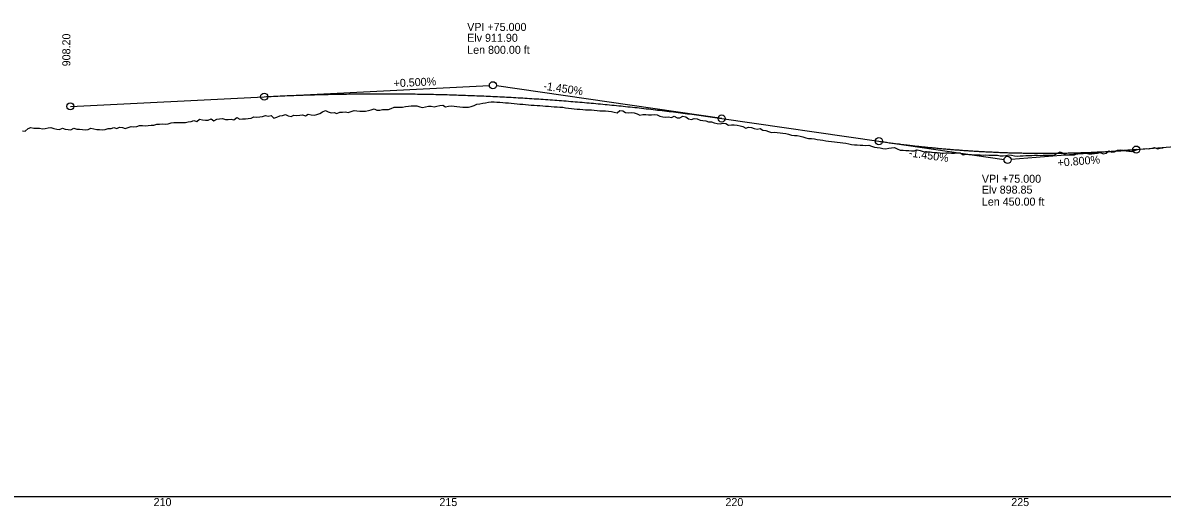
# Model space of a CAD drawing. Extents: x 5180909 to 5237144, y 3695282 to 3720102.
# Drawn here: x 5224513 to 5226506, y 3697765 to 3698610 of the extents above; entities that cross this region are included whole.
import ezdxf

# ---------------------------------------------------------------- set-up
doc = ezdxf.new("R2010")
doc.units = 0
for name, color, linetype in [('dsnEntranceGranular', 7, 'Continuous'), ('dsnShoulderGran', 7, 'Continuous'), ('dsnShoulderPaved', 7, 'Continuous'), ('dsnStgShadingPropGrdLim', 7, 'Continuous'), ('EdgeShoulder', 7, 'Continuous'), ('Entrance', 7, 'Continuous')]:
    doc.layers.add(name, color=color, linetype=linetype)

msp = doc.modelspace()

# ---------------------------------------------------------------- linework, layer by layer
at = {"layer": 'dsnEntranceGranular'}
msp.add_line((5221643.6, 3697782), (5237143.6, 3697782), dxfattribs=at)
at = {"layer": 'dsnShoulderPaved'}
for points in [[(5225142.7, 3698458.4), (5225147.7, 3698458.6), (5225152.7, 3698458.8), (5225157.7, 3698460.3), (5225162.7, 3698462.5), (5225167.7, 3698462.3), (5225172.7, 3698462.3), (5225177.7, 3698462.7), (5225182.7, 3698463.7), (5225187.7, 3698464.6), (5225192.7, 3698464.9), (5225197.7, 3698465), (5225202.7, 3698465.1), (5225207.7, 3698463.2), (5225212.7, 3698462.2), (5225217.7, 3698463), (5225222.7, 3698464.2), (5225227.7, 3698464.3), (5225232.7, 3698463.3), (5225237.7, 3698464.4), (5225242.7, 3698465.4), (5225247.7, 3698466.2), (5225252.7, 3698463.1), (5225257.7, 3698464.5), (5225262.7, 3698465), (5225267.7, 3698464.5), (5225272.7, 3698463.7), (5225277.7, 3698463.1), (5225282.7, 3698462.7), (5225287.7, 3698462.3), (5225292.7, 3698462.5), (5225297.7, 3698463.5), (5225302.7, 3698465.3), (5225307.7, 3698467.8), (5225312.7, 3698468.7), (5225317.7, 3698469.5), (5225322.7, 3698470.3), (5225327.7, 3698471.5), (5225332.7, 3698472), (5225337.7, 3698471.8), (5225342.7, 3698471.6), (5225347.7, 3698471.5), (5225352.7, 3698470.9), (5225357.7, 3698470.4), (5225362.7, 3698470), (5225367.7, 3698469.6), (5225372.7, 3698469.1), (5225377.7, 3698468.7), (5225382.7, 3698468.1), (5225387.7, 3698467.6), (5225392.7, 3698467.1), (5225397.7, 3698466.6), (5225402.7, 3698466.1), (5225407.7, 3698465.8), (5225412.7, 3698465.5), (5225417.7, 3698465.3), (5225422.7, 3698465), (5225427.7, 3698464.6), (5225432.7, 3698464.3), (5225437.7, 3698463.6), (5225442.7, 3698463.3), (5225447.7, 3698463.1), (5225452.7, 3698462.8), (5225457.7, 3698462.3), (5225462.7, 3698461.6), (5225467.7, 3698460.9), (5225472.7, 3698460.2), (5225477.7, 3698459.5), (5225482.7, 3698459.3), (5225487.7, 3698459), (5225492.7, 3698458.6), (5225497.7, 3698458.2), (5225502.7, 3698458), (5225507.7, 3698457.8), (5225512.7, 3698457.3), (5225517.7, 3698456.8), (5225522.7, 3698456.3), (5225527.7, 3698456.2), (5225532.7, 3698455.9), (5225537.7, 3698455.6), (5225542.7, 3698454.8), (5225547.7, 3698453.8), (5225552.7, 3698452.8), (5225557.7, 3698456.9), (5225562.7, 3698456.2), (5225567.7, 3698453.3), (5225572.7, 3698452.5), (5225577.7, 3698453), (5225582.7, 3698452.9), (5225587.7, 3698451.2), (5225592.7, 3698448.5), (5225597.7, 3698449.5), (5225602.7, 3698449.5), (5225607.7, 3698449), (5225612.7, 3698449.3), (5225617.7, 3698449.5), (5225622.7, 3698449.3), (5225627.7, 3698446.9), (5225632.7, 3698445.9), (5225637.7, 3698445.3), (5225642.7, 3698445.5)], [(5224642.7, 3698423.3), (5224647.7, 3698423.3), (5224652.7, 3698423.2), (5224657.7, 3698423.4), (5224662.7, 3698425.1), (5224667.7, 3698425.5), (5224672.7, 3698426.8), (5224677.7, 3698425.4), (5224682.7, 3698427.7), (5224687.7, 3698427.2), (5224692.7, 3698425.3), (5224697.7, 3698426.8), (5224702.7, 3698428.7), (5224707.7, 3698428.1), (5224712.7, 3698428.7), (5224717.7, 3698430.4), (5224722.7, 3698430.3), (5224727.7, 3698430.2), (5224732.7, 3698430.7), (5224737.7, 3698431.4), (5224742.7, 3698431.2), (5224747.7, 3698433.1), (5224752.7, 3698432.8), (5224757.7, 3698433.2), (5224762.7, 3698432.7), (5224767.7, 3698433.4), (5224772.7, 3698435), (5224777.7, 3698435.5), (5224782.7, 3698435.6), (5224787.7, 3698435.7), (5224792.7, 3698435.7), (5224797.7, 3698435.7), (5224802.7, 3698436.9), (5224807.7, 3698437.4), (5224812.7, 3698439), (5224817.7, 3698437.8), (5224822.7, 3698441.5), (5224827.7, 3698440.7), (5224832.7, 3698439.7), (5224837.7, 3698439.9), (5224842.7, 3698441.9), (5224847.7, 3698438.7), (5224852.7, 3698441.7), (5224857.7, 3698441.9), (5224862.7, 3698442.6), (5224867.7, 3698441.3), (5224872.7, 3698441), (5224877.7, 3698441.7), (5224882.7, 3698440.2), (5224887.7, 3698444.3), (5224892.7, 3698441.7), (5224897.7, 3698442.1), (5224902.7, 3698442.2), (5224907.7, 3698443), (5224912.7, 3698443.4), (5224917.7, 3698445.7), (5224922.7, 3698445.2), (5224927.7, 3698445.4), (5224932.7, 3698446.2), (5224937.7, 3698447.8), (5224942.7, 3698447), (5224947.7, 3698447.9), (5224952.7, 3698443.2), (5224957.7, 3698445.1), (5224962.7, 3698447.2), (5224967.7, 3698448.2), (5224972.7, 3698449.7), (5224977.7, 3698447.7), (5224982.7, 3698446.3), (5224987.7, 3698448.6), (5224992.7, 3698448), (5224997.7, 3698448.7), (5225002.7, 3698449.2), (5225007.7, 3698447.7), (5225012.7, 3698450.1), (5225017.7, 3698449.1), (5225022.7, 3698448.8), (5225027.7, 3698449.5), (5225032.7, 3698451.7), (5225037.7, 3698454.4), (5225042.7, 3698456.7), (5225047.7, 3698454.7), (5225052.7, 3698452.9), (5225057.7, 3698453.4), (5225062.7, 3698451.6), (5225067.7, 3698453.9), (5225072.7, 3698454), (5225077.7, 3698454.5), (5225082.7, 3698453), (5225087.7, 3698455.2), (5225092.7, 3698456.9), (5225097.7, 3698456.2), (5225102.7, 3698455.5), (5225107.7, 3698455.4), (5225112.7, 3698455.8), (5225117.7, 3698456.8), (5225122.7, 3698457.9), (5225127.7, 3698459.8), (5225132.7, 3698457.5), (5225137.7, 3698457.4), (5225142.7, 3698458.4)], [(5225642.7, 3698445.5), (5225647.7, 3698444.6), (5225652.7, 3698446.8), (5225657.7, 3698443.7), (5225662.7, 3698444.1), (5225667.7, 3698446.8), (5225672.7, 3698445.4), (5225677.7, 3698442.4), (5225682.7, 3698440.9), (5225687.7, 3698442.6), (5225692.7, 3698442.3), (5225697.7, 3698439.6), (5225702.7, 3698439.3), (5225707.7, 3698438.7), (5225712.7, 3698436.9), (5225717.7, 3698437.1), (5225722.7, 3698435.4), (5225727.7, 3698433.9), (5225732.7, 3698433.4), (5225737.7, 3698434.6), (5225742.7, 3698434.3), (5225747.7, 3698431), (5225752.7, 3698431.9), (5225757.7, 3698431.7), (5225762.7, 3698431.3), (5225767.7, 3698429.9), (5225772.7, 3698428.7), (5225777.7, 3698426.1), (5225782.7, 3698427.9), (5225787.7, 3698427), (5225792.7, 3698425.4), (5225797.7, 3698424), (5225802.7, 3698425), (5225807.7, 3698422.2), (5225812.7, 3698421.8), (5225817.7, 3698420.3), (5225822.7, 3698418.4), (5225827.7, 3698418.7), (5225832.7, 3698418.4), (5225837.7, 3698417.9), (5225842.7, 3698417.2), (5225847.7, 3698416.7), (5225852.7, 3698415.1), (5225857.7, 3698413.7), (5225862.7, 3698412.8), (5225867.7, 3698412.8), (5225872.7, 3698412), (5225877.7, 3698410.9), (5225882.7, 3698409.2), (5225887.7, 3698408), (5225892.7, 3698407.9), (5225897.7, 3698407.3), (5225902.7, 3698406.3), (5225907.7, 3698405.4), (5225912.7, 3698404.7), (5225917.7, 3698404), (5225922.7, 3698403.1), (5225927.7, 3698402.5), (5225932.7, 3698401.9), (5225937.7, 3698401.2), (5225942.7, 3698400.8), (5225947.7, 3698400.3), (5225952.7, 3698399.4), (5225957.7, 3698398.6), (5225962.7, 3698397.4), (5225967.7, 3698397), (5225972.7, 3698396.6), (5225977.7, 3698396), (5225982.7, 3698396), (5225987.7, 3698395.7), (5225992.7, 3698396.3), (5225997.7, 3698394.3), (5226002.7, 3698392.6), (5226007.7, 3698392), (5226012.7, 3698391.4), (5226017.7, 3698390.6), (5226022.7, 3698389.9), (5226027.7, 3698390.9), (5226032.7, 3698391.2), (5226037.7, 3698391.8), (5226042.7, 3698389.6), (5226047.7, 3698387.6), (5226052.7, 3698387.2), (5226057.7, 3698386.9), (5226062.7, 3698386.7), (5226067.7, 3698386.3), (5226072.7, 3698386.4), (5226077.7, 3698387.7), (5226082.7, 3698386.6), (5226087.7, 3698385.1), (5226092.7, 3698384.5), (5226097.7, 3698384.2), (5226102.7, 3698383.8), (5226107.7, 3698383.5), (5226112.7, 3698383.3), (5226117.7, 3698382.6), (5226122.7, 3698382.2), (5226127.7, 3698382.9), (5226132.7, 3698382.6), (5226137.7, 3698382.2), (5226142.7, 3698381.9)], [(5224512.7, 3698421.4), (5224517.7, 3698420.4), (5224522.7, 3698425.1), (5224527.7, 3698427.3), (5224532.7, 3698425.6), (5224537.7, 3698425.6), (5224542.7, 3698425.7), (5224547.7, 3698424.6), (5224552.7, 3698425.3), (5224557.7, 3698426.3), (5224562.7, 3698426.9), (5224567.7, 3698425), (5224572.7, 3698424.1), (5224577.7, 3698423.4), (5224582.7, 3698425.8), (5224587.7, 3698424.3), (5224592.7, 3698423.4), (5224597.7, 3698422.9), (5224602.7, 3698426.1), (5224607.7, 3698424.2), (5224612.7, 3698424.4), (5224617.7, 3698423.3), (5224622.7, 3698422.8), (5224627.7, 3698423.3), (5224632.7, 3698425.7), (5224637.7, 3698424.9), (5224642.7, 3698423.3)], [(5226142.7, 3698381.9), (5226147.7, 3698382.5), (5226152.7, 3698382.8), (5226157.7, 3698379), (5226162.7, 3698380.5), (5226167.7, 3698380), (5226172.7, 3698379.7), (5226177.7, 3698379.5), (5226182.7, 3698379.1), (5226187.7, 3698379.2), (5226192.7, 3698378.9), (5226197.7, 3698379.3), (5226202.7, 3698378.9), (5226207.7, 3698378.5), (5226212.7, 3698378.5), (5226217.7, 3698378.5), (5226222.7, 3698377.7), (5226227.7, 3698377.5), (5226232.7, 3698378.1), (5226237.7, 3698379.4), (5226242.7, 3698378.4), (5226247.7, 3698377.5), (5226252.7, 3698377.1), (5226257.7, 3698377.2), (5226262.7, 3698377.6), (5226267.7, 3698378), (5226272.7, 3698378.2), (5226277.7, 3698378.3), (5226282.7, 3698378.5), (5226287.7, 3698378.4), (5226292.7, 3698378.3), (5226297.7, 3698378.4), (5226302.7, 3698378.7), (5226307.7, 3698378.8), (5226312.7, 3698378.9), (5226317.7, 3698379.1), (5226322.7, 3698381.9), (5226327.7, 3698384.2), (5226332.7, 3698382.1), (5226337.7, 3698379.5), (5226342.7, 3698379.3), (5226347.7, 3698379.2), (5226352.7, 3698379.4), (5226357.7, 3698381.5), (5226362.7, 3698381.8), (5226367.7, 3698381.4), (5226372.7, 3698381.9), (5226377.7, 3698380.8), (5226382.7, 3698381), (5226387.7, 3698381.7), (5226392.7, 3698382.4), (5226397.7, 3698383.2), (5226402.7, 3698381.2), (5226407.7, 3698381.9), (5226412.7, 3698386.4), (5226417.7, 3698383.8), (5226422.7, 3698384.6), (5226427.7, 3698387.6), (5226432.7, 3698388), (5226437.7, 3698387.3), (5226442.7, 3698386), (5226447.7, 3698385.6), (5226452.7, 3698384.8), (5226457.7, 3698386.7), (5226462.7, 3698388.6), (5226467.7, 3698389.2), (5226472.7, 3698389.5), (5226477.7, 3698390.5), (5226482.7, 3698389.7), (5226487.7, 3698390.7), (5226492.7, 3698392.1), (5226497.7, 3698389.9), (5226502.7, 3698390.8), (5226507.7, 3698391.6)]]:
    msp.add_lwpolyline(points, dxfattribs=at)
at = {"layer": 'dsnStgShadingPropGrdLim'}
for p, q in [((5224596.6, 3698464), (5224935.6, 3698480.9)), ((5226460.6, 3698388.4), (5227435.6, 3698466.4)), ((5225735.6, 3698442.9), (5226010.6, 3698403.1))]:
    msp.add_line(p, q, dxfattribs=at)
for points in [[(5224935.6, 3698480.9), (5224951.6, 3698481.7), (5224967.6, 3698482.4), (5224983.6, 3698483.1), (5224999.6, 3698483.6), (5225015.6, 3698484.2), (5225031.6, 3698484.6), (5225047.6, 3698485), (5225063.6, 3698485.3), (5225079.6, 3698485.6), (5225095.6, 3698485.8), (5225111.6, 3698486), (5225127.6, 3698486), (5225143.6, 3698486.1), (5225159.6, 3698486), (5225175.6, 3698485.9), (5225191.6, 3698485.8), (5225207.6, 3698485.5), (5225223.6, 3698485.2), (5225239.6, 3698484.9), (5225255.6, 3698484.5), (5225271.6, 3698484), (5225287.6, 3698483.4), (5225303.6, 3698482.8), (5225319.6, 3698482.2), (5225335.6, 3698481.4), (5225351.6, 3698480.6), (5225367.6, 3698479.8), (5225383.6, 3698478.9), (5225399.6, 3698477.9), (5225415.6, 3698476.9), (5225431.6, 3698475.8), (5225447.6, 3698474.6), (5225463.6, 3698473.4), (5225479.6, 3698472.1), (5225495.6, 3698470.7), (5225511.6, 3698469.3), (5225527.6, 3698467.8), (5225543.6, 3698466.3), (5225559.6, 3698464.7), (5225575.6, 3698463), (5225591.6, 3698461.3), (5225607.6, 3698459.5), (5225623.6, 3698457.6), (5225639.6, 3698455.7), (5225655.6, 3698453.8), (5225671.6, 3698451.7), (5225687.6, 3698449.6), (5225703.6, 3698447.5), (5225719.6, 3698445.2), (5225735.6, 3698442.9)], [(5226010.6, 3698403.1), (5226019.6, 3698401.8), (5226028.6, 3698400.5), (5226037.6, 3698399.3), (5226046.6, 3698398.2), (5226055.6, 3698397), (5226064.6, 3698396), (5226073.6, 3698394.9), (5226082.6, 3698393.9), (5226091.6, 3698393), (5226100.6, 3698392), (5226109.6, 3698391.2), (5226118.6, 3698390.3), (5226127.6, 3698389.5), (5226136.6, 3698388.8), (5226145.6, 3698388), (5226154.6, 3698387.4), (5226163.6, 3698386.7), (5226172.6, 3698386.1), (5226181.6, 3698385.6), (5226190.6, 3698385.1), (5226199.6, 3698384.6), (5226208.6, 3698384.2), (5226217.6, 3698383.8), (5226226.6, 3698383.4), (5226235.6, 3698383.1), (5226244.6, 3698382.8), (5226253.6, 3698382.6), (5226262.6, 3698382.4), (5226271.6, 3698382.2), (5226280.6, 3698382.1), (5226289.6, 3698382.1), (5226298.6, 3698382), (5226307.6, 3698382), (5226316.6, 3698382.1), (5226325.6, 3698382.2), (5226334.6, 3698382.3), (5226343.6, 3698382.5), (5226352.6, 3698382.7), (5226361.6, 3698383), (5226370.6, 3698383.3), (5226379.6, 3698383.6), (5226388.6, 3698384), (5226397.6, 3698384.4), (5226406.6, 3698384.8), (5226415.6, 3698385.3), (5226424.6, 3698385.9), (5226433.6, 3698386.5), (5226442.6, 3698387.1), (5226451.6, 3698387.7), (5226460.6, 3698388.4)]]:
    msp.add_spline(points, degree=3, dxfattribs=at)
at = {"layer": 'Entrance'}
for p, q in [((5224935.6, 3698480.9), (5225329.4, 3698500.6)), ((5225735.6, 3698442.9), (5225341.8, 3698500)), ((5226010.6, 3698403.1), (5226229.4, 3698371.3)), ((5226460.6, 3698388.4), (5226241.8, 3698370.9))]:
    msp.add_line(p, q, dxfattribs=at)
for centre in [(5225335.6, 3698500.9), (5224935.6, 3698480.9), (5224596.6, 3698464), (5225735.6, 3698442.9), (5226010.6, 3698403.1), (5226460.6, 3698388.4), (5226235.6, 3698370.4)]:
    msp.add_circle(centre, 6.25, dxfattribs=at)

# ---------------------------------------------------------------- texts
at = {"layer": 'dsnShoulderGran'}
for s, p in [('210', (5224742.2, 3697765)), ('215', (5225242, 3697765)), ('220', (5225742.2, 3697765)), ('225', (5226242, 3697765))]:
    msp.add_text(s, height=14, dxfattribs=at).set_placement(p)
at = {"layer": 'EdgeShoulder'}
for s, p in [('VPI +75.000', (5225290.6, 3698595.9)), ('Elv 911.90', (5225290.6, 3698576.9)), ('Len 800.00 ft', (5225290.6, 3698555.9)), ('VPI +75.000', (5226190.6, 3698330.4)), ('Elv 898.85', (5226190.6, 3698311.4)), ('Len 450.00 ft', (5226190.6, 3698290.4))]:
    msp.add_text(s, height=14, dxfattribs=at).set_placement(p)
for s, rotation, p in [('908.20', 90, (5224596.6, 3698534)), ('+0.500%', 2.8624, (5225162.2, 3698497.3)), ('-1.450%', 351.7496, (5225423.1, 3698493.3)), ('-1.450%', 351.7496, (5226062.4, 3698376.4)), ('+0.800%', 4.5739, (5226323.5, 3698358.4))]:
    msp.add_text(s, height=14, rotation=rotation, dxfattribs=at).set_placement(p)

doc.saveas('drawing.dxf')
